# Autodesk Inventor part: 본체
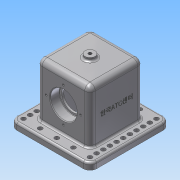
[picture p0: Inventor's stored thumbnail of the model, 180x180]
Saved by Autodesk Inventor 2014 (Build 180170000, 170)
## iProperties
Created: 2018-11
Part Number: 본체
Material: 알루미늄 6061
Document SubType Name: Modeling
Designer: 703
Density: 2.71 g/cm^3
Appearance: 알루미늄 - 평지
Mass: 1009.54 g
Surface Area: 801.949 cm^2
Volume: 372.524 cm^3
Author: 703
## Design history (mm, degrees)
sketch "스케치2"
  geometry: L1 (-60, 60)-(60, 60); L2 (60, 60)-(60, -60); L3 (60, -60)-(-60, -60); L4 (-60, -60)-(-60, 60); L5 (-60, 60)-(60, -60); L6 (60, 60)-(-60, -60); 1 further point
  constraints: 12 end point, 2 midpoint, 2 parallel, 1 horizontal, 1 perpendicular
  dimensions: "d0" = 120 distance of L2.end L3.end; "d1" = 120 distance of L1.end L2.end
extrude "돌출1" new body sketch "스케치2" distance "d2" = 10; taper "d3" = 0 deg
sketch "스케치3"
  geometry: L1 (-40, -40)-(40, -40); L2 (40, -40)-(40, 40); L3 (40, 40)-(-40, 40); L4 (-40, 40)-(-40, -40); L5 (-40, -40)-(40, 40); L6 (40, -40)-(-40, 40); 1 further point
  constraints: 12 end point, 2 midpoint, 2 parallel, 1 horizontal, 1 perpendicular
  dimensions: "d4" = 80 distance of L3.end L2.end; "d5" = 80 distance of L2.end L1.end
extrude "돌출2" join sketch "스케치3" distance "d6" = 80; taper "d7" = 0 deg
sketch "스케치4"
  geometry: C1 r 7.5 at (0, 0); 1 further point
  constraints: 1 centre point, 1 coincident
  dimensions: "d8" = 15 diameter of C1
extrude "돌출3" join sketch "스케치4" distance "d9" = 5; taper "d10" = 0 deg
sketch "스케치5"
  geometry: L1 (-30, -23)-(30, -23); L2 (30, -23)-(30, 23); L3 (30, 23)-(-30, 23); L4 (-30, 23)-(-30, -23); L5 (-30, -23)-(30, 23); L6 (30, -23)-(-30, 23); 1 further point
  constraints: 12 end point, 2 midpoint, 2 parallel, 1 horizontal, 1 perpendicular
  dimensions: "d11" = 60 distance of L2.end L3.end; "d12" = 46 distance of L1.end L2.end
extrude "돌출4" cut sketch "스케치5" distance "d13" = 80; taper "d14" = 0 deg
node "작업 평면1"
hole "구멍2" diameter "d28" = 4.917; stored, may be unused: countersink angle "d32" = 90 deg, drill point angle "d34" = 0 deg; dims "d24" = 10, "d25" = 10, "d29" = 6, "d30" = 40, "d31" = 14, "d33" = 17
fillet "모깎기1" dims "d35" = 8
fillet "모깎기2" dims "d36" = 8
sketch "스케치6"
  geometry: L1 (92, -10)-(-28, -10) reference; 3 further points
  constraints: 1 midpoint, 1 vertical alignment
  dimensions: "d37" = 48 distance from line of L1 point (32, 38)
hole "구멍3" sketch "스케치6" at (32, 38) diameter "d38" = 33; stored, may be unused: countersink angle "d42" = 90 deg, drill point angle "d44" = 0 deg; dims "d39" = 6, "d40" = 40, "d41" = 14, "d43" = 17
chamfer "모따기1" distance "d45" = 1; stored, may be unused: second distance "d46" = 2, angle "d47" = 45 deg
fillet "모깎기3" dims "d48" = 0.6
sketch "스케치7"
  geometry: C1 r 21 at (32, 38) reference; 2 further points
  constraints: 1 vertical alignment
  dimensions: "d49" = 26 distance of C1.centre point (32, 64)
hole "구멍4" sketch "스케치7" at (32, 64) diameter "d50" = 3.242; stored, may be unused: countersink angle "d54" = 90 deg, drill point angle "d56" = 118 deg; dims "d51" = 8, "d52" = 40, "d53" = 14, "d55" = 10
fillet "모깎기4" dims "d60" = 10
fillet "모깎기5" dims "d61" = 3
fillet "모깎기6" dims "d62" = 3
sketch "스케치8"
  geometry: L1 (0, 0)-(64, 0) reference; L2 (82, -82)-(-18, -82) reference; 3 further points
  constraints: 1 midpoint, 1 vertical alignment, 1 other
  dimensions: "d78" = 48 distance from line of L2 point (32, -34)
feature "엠보싱1" sketch "스케치8" dims "d0" = 120, "d1" = 120, "d79" = 0.5, "d80" = 0
sketch "스케치10"
  geometry: C1 r 3.3 at (50, -50); A1 r 7 centre (50, -50) between (50, -57) and (57, -50) reference; 1 further point
  constraints: 1 centre point, 1 coincident
  dimensions: "d106" = 6.6 diameter of C1
extrude "돌출5" cut sketch "스케치10" stored distance "d107" = 80; taper "d108" = 0 deg
node "솔리드1"
mirror "대칭2"
pattern_circular "원형 패턴1" dims angle "d58" = 360 deg
mirror "대칭3"
pattern_linear "직사각형 패턴5" dims "d111" = 10
pattern_linear "직사각형 패턴6" dims "d117" = 25
